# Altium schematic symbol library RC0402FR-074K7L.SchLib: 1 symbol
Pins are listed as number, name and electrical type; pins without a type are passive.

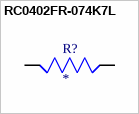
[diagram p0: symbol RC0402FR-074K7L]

## RC0402FR-074K7L
designator R?
4.7 kOhms Â±1% 0.063W, 1/16W Chip Resistor 0402 (1005 Metric) Moisture Resistant Thick Film; MF: Yageo; MP: RC0402FR-074K7L
footprint RESC1005X40
pins: 1, 2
